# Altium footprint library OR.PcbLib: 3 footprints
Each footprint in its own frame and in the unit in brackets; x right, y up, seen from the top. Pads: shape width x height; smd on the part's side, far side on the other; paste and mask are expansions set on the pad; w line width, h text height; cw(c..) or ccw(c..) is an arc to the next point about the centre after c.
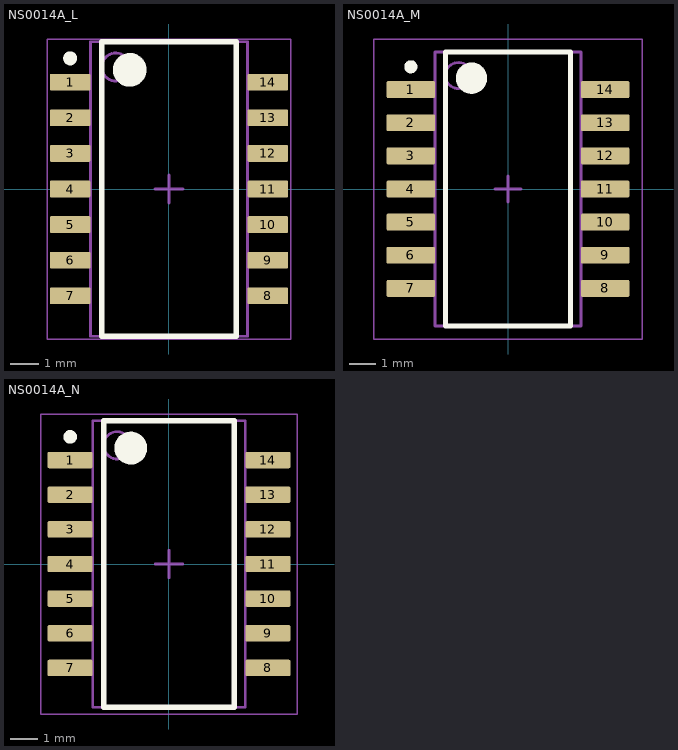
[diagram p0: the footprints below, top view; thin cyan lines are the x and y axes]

## NS0014A_L [mm] "SOP, 14-Leads, Body 10.2x5.3mm, Pitch 1.27mm, IPC High Density"
height 2
pads (14):
  rrect17% 1.45x0.6 smd: 1(-3.525,3.81) 2(-3.525,2.54) 3(-3.525,1.27) 4(-3.525,0) 5(-3.525,-1.27) 6(-3.525,-2.54) 7(-3.525,-3.81) 8(3.525,-3.81) 9(3.525,-2.54) 10(3.525,-1.27) 11(3.525,0) 12(3.525,1.27) 13(3.525,2.54) 14(3.525,3.81)
Top Overlay:
  circle w0.6: c-1.4,4.25 r0.3
  circle w0.25: c-3.525,4.66 r0.125
  lines w0.2: -2.4,-5.25 2.4,-5.25 2.4,5.25 -2.4,5.25 -2.4,-5.25
Mechanical 1:
  text ".Designator" at -1.524,-0.508 h1.02
Mechanical 13:
  circle w0.1: c-1.9,4.35 r0.5
  lines w0.1: -2.8,-5.25 2.8,-5.25 2.8,5.25 -2.8,5.25 -2.8,-5.25
Mechanical 15:
  lines w0.05: -4.35,-5.35 4.35,-5.35 4.35,5.35 -4.35,5.35 -4.35,-5.35
  lines w0.1: -0.5,0 0.5,0 ; 0,-0.5 0,0.5
3D body: height 2, standoff 0.05, extent -2.8,-5.25 2.8,5.25

## NS0014A_M [mm] "SOIC,14-Leads,Body 10.5x5.6mm,Pitch 1.27mm,IPC Low Density"
height 2
pads (14):
  rrect15% 1.85x0.65 smd: 1(-3.725,3.81) 2(-3.725,2.54) 3(-3.725,1.27) 4(-3.725,0) 5(-3.725,-1.27) 6(-3.725,-2.54) 7(-3.725,-3.81) 8(3.725,-3.81) 9(3.725,-2.54) 10(3.725,-1.27) 11(3.725,0) 12(3.725,1.27) 13(3.725,2.54) 14(3.725,3.81)
Top Overlay:
  circle w0.6: c-1.4,4.25 r0.3
  circle w0.25: c-3.725,4.685 r0.125
  lines w0.2: -2.4,-5.25 2.4,-5.25 2.4,5.25 -2.4,5.25 -2.4,-5.25
Mechanical 1:
  text ".Designator" at -1.524,-0.508 h1.02
Mechanical 13:
  circle w0.1: c-1.9,4.35 r0.5
  lines w0.1: -2.8,-5.25 2.8,-5.25 2.8,5.25 -2.8,5.25 -2.8,-5.25
Mechanical 15:
  lines w0.05: -5.15,-5.75 5.15,-5.75 5.15,5.75 -5.15,5.75 -5.15,-5.75
  lines w0.1: -0.5,0 0.5,0 ; 0,-0.5 0,0.5
3D body: height 2, standoff 0.05, extent -2.8,-5.25 2.8,5.25

## NS0014A_N [mm] "SOIC,14-Leads,Body 10.5x5.6mm,Pitch 1.27mm,IPC Medium Density"
height 2
pads (14):
  rrect17% 1.65x0.6 smd: 1(-3.625,3.81) 2(-3.625,2.54) 3(-3.625,1.27) 4(-3.625,0) 5(-3.625,-1.27) 6(-3.625,-2.54) 7(-3.625,-3.81) 8(3.625,-3.81) 9(3.625,-2.54) 10(3.625,-1.27) 11(3.625,0) 12(3.625,1.27) 13(3.625,2.54) 14(3.625,3.81)
Top Overlay:
  circle w0.6: c-1.4,4.25 r0.3
  circle w0.25: c-3.625,4.66 r0.125
  lines w0.2: -2.4,-5.25 2.4,-5.25 2.4,5.25 -2.4,5.25 -2.4,-5.25
Mechanical 1:
  text ".Designator" at -1.524,-0.508 h1.02
Mechanical 13:
  circle w0.1: c-1.9,4.35 r0.5
  lines w0.1: -2.8,-5.25 2.8,-5.25 2.8,5.25 -2.8,5.25 -2.8,-5.25
Mechanical 15:
  lines w0.05: -4.7,-5.5 4.7,-5.5 4.7,5.5 -4.7,5.5 -4.7,-5.5
  lines w0.1: -0.5,0 0.5,0 ; 0,-0.5 0,0.5
3D body: height 2, standoff 0.05, extent -2.8,-5.25 2.8,5.25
